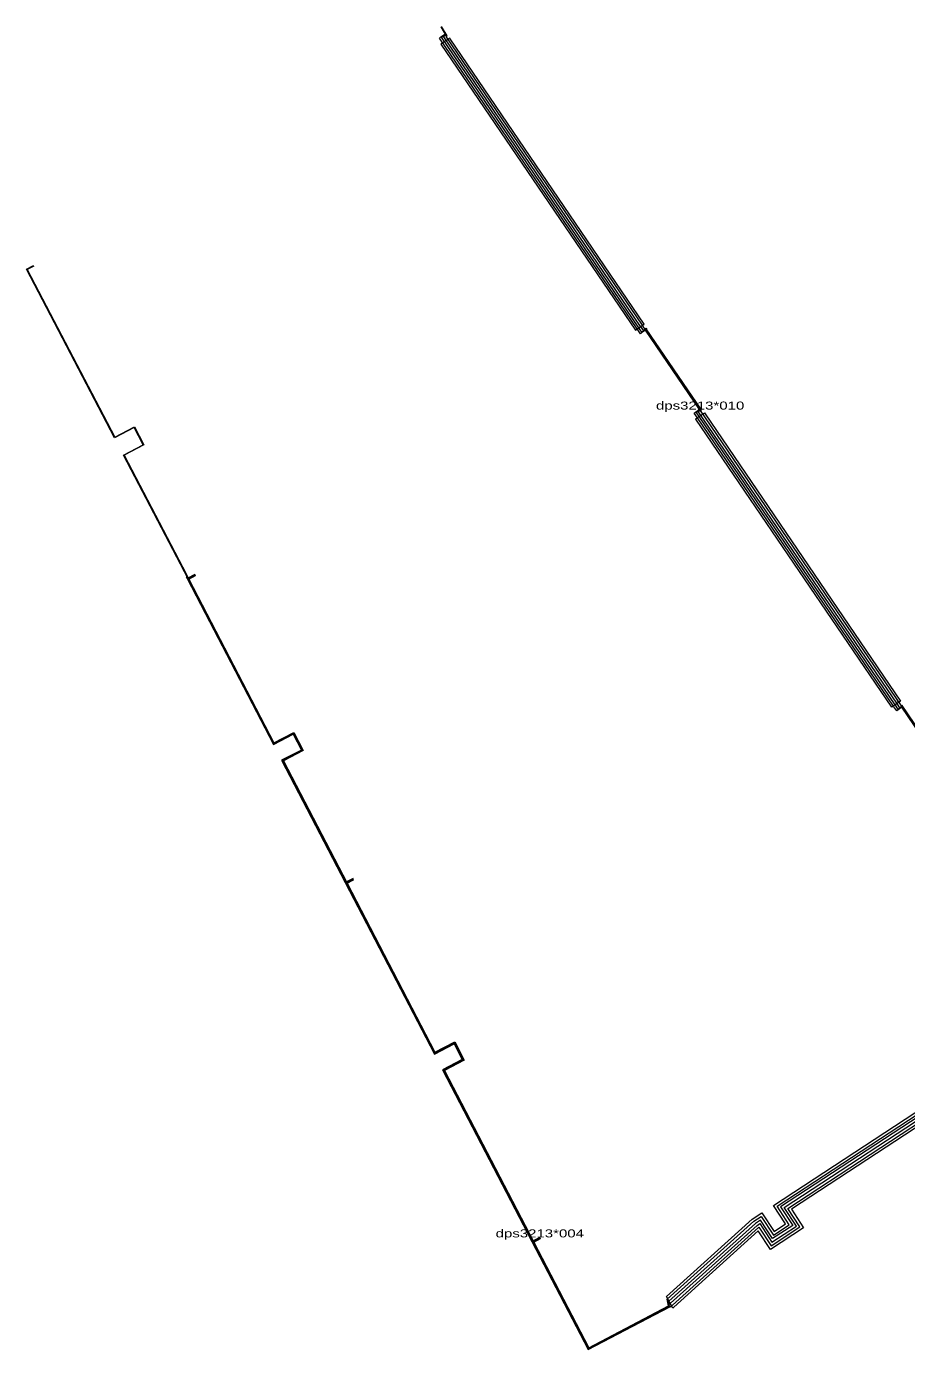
# Model space of a CAD drawing. Extents: x -473467 to -473049, y -1106745 to -1106181.
# Drawn here: x -473467 to -473368.1, y -1106572 to -1106423.3 of the extents above; entities that cross this region are included whole.
import ezdxf
from ezdxf.enums import TextEntityAlignment as Align

# ---------------------------------------------------------------- set-up
doc = ezdxf.new("R2010")
doc.units = 0
doc.header["$LTSCALE"] = 0.36
doc.header["$PDMODE"] = 32
doc.header["$PDSIZE"] = 0.18
doc.layers.add('11', color=7, linetype='Continuous', lineweight=13)
doc.layers.add('17', color=7, linetype='Continuous', lineweight=13)
doc.layers.add('19', color=7, linetype='Continuous')

msp = doc.modelspace()

# ---------------------------------------------------------------- linework, layer by layer
at = {"layer": '11'}
for points in [[(-473362.859, -1106508.966), (-473362.452, -1106508.691), (-473368.583, -1106499.672), (-473368.855, -1106499.858), (-473369.127, -1106499.459), (-473391.519, -1106466.551), (-473391.231, -1106466.356), (-473397.396, -1106457.287), (-473397.406, -1106457.272), (-473397.679, -1106457.458), (-473397.908, -1106457.12), (-473397.988, -1106457.003), (-473420.06, -1106424.535), (-473420.167, -1106424.378), (-473419.892, -1106424.19), (-473420.43, -1106423.291)], [(-473359.708, -1106529.352), (-473359.708, -1106529.352), (-473364.632, -1106521.935), (-473357.166, -1106516.999), (-473362.207, -1106509.406), (-473362.511, -1106508.948), (-473362.584, -1106508.841), (-473362.382, -1106508.704), (-473368.57, -1106499.603), (-473368.652, -1106499.659), (-473391.278, -1106466.448), (-473391.162, -1106466.369), (-473397.365, -1106457.244), (-473397.393, -1106457.203), (-473397.434, -1106457.231), (-473397.509, -1106457.281), (-473397.615, -1106457.124), (-473397.71, -1106456.985), (-473397.79, -1106456.868), (-473419.862, -1106424.4), (-473419.754, -1106424.327), (-473420.387, -1106423.265)], [(-473398.317, -1106457.373), (-473398.385, -1106457.273), (-473420.62, -1106424.565), (-473420.446, -1106424.447), (-473420.061, -1106424.184)], [(-473398.107, -1106457.255), (-473398.187, -1106457.138), (-473420.393, -1106424.471), (-473420.377, -1106424.46), (-473420.009, -1106424.21)], [(-473362.763, -1106543.227), (-473382.253, -1106555.985), (-473380.883, -1106558.077), (-473383.15, -1106559.56), (-473384.519, -1106557.469), (-473385.082, -1106557.837), (-473394.829, -1106566.605), (-473394.883, -1106566.653), (-473394.796, -1106567.142), (-473403.833, -1106571.891), (-473410.077, -1106559.922), (-473409.288, -1106559.51), (-473410.077, -1106559.922), (-473420.123, -1106540.615), (-473417.905, -1106539.463), (-473418.919, -1106537.512), (-473421.138, -1106538.666), (-473431.069, -1106519.572), (-473430.298, -1106519.17), (-473431.069, -1106519.572), (-473438.225, -1106505.815), (-473436.006, -1106504.662), (-473437.02, -1106502.711), (-473439.239, -1106503.866), (-473448.859, -1106485.374), (-473448.07, -1106484.962), (-473448.859, -1106485.374), (-473456.126, -1106471.452), (-473453.909, -1106470.295), (-473454.927, -1106468.344), (-473457.144, -1106469.501), (-473467.049, -1106450.567), (-473466.249, -1106450.156)], [(-473466.225, -1106450.205), (-473466.981, -1106450.588), (-473457.123, -1106469.434), (-473454.906, -1106468.277), (-473453.842, -1106470.316), (-473456.058, -1106471.473), (-473449.065, -1106484.872), (-473448.792, -1106485.395), (-473448.043, -1106485.006), (-473448.792, -1106485.395), (-473439.218, -1106503.798), (-473436.999, -1106502.644), (-473435.939, -1106504.684), (-473438.158, -1106505.836), (-473431.001, -1106519.593), (-473430.258, -1106519.212), (-473431.001, -1106519.593), (-473421.116, -1106538.599), (-473418.898, -1106537.445), (-473417.837, -1106539.484), (-473420.056, -1106540.637), (-473410.009, -1106559.943), (-473409.252, -1106559.553), (-473410.009, -1106559.943), (-473403.812, -1106571.823), (-473394.854, -1106567.116), (-473394.997, -1106566.365), (-473385.26, -1106557.606), (-473384.435, -1106557.066), (-473383.066, -1106559.158), (-473381.286, -1106557.993), (-473382.655, -1106555.901), (-473362.678, -1106542.825)], [(-473391.395, -1106466.346), (-473391.37, -1106466.329), (-473397.433, -1106457.411), (-473397.846, -1106457.692), (-473398.02, -1106457.81), (-473398.317, -1106457.373)], [(-473391.327, -1106466.36), (-473391.301, -1106466.342), (-473397.419, -1106457.342), (-473397.833, -1106457.623), (-473397.849, -1106457.634), (-473398.107, -1106457.255)], [(-473369.51, -1106499.749), (-473369.562, -1106499.673), (-473391.592, -1106467.266), (-473391.957, -1106466.728), (-473391.395, -1106466.346)], [(-473369.325, -1106499.594), (-473369.363, -1106499.538), (-473391.393, -1106467.131), (-473391.731, -1106466.635), (-473391.714, -1106466.623), (-473391.327, -1106466.36)], [(-473449.092, -1106485.144), (-473448.994, -1106485.331), (-473448.108, -1106484.869), (-473448.994, -1106485.331), (-473446.482, -1106490.16), (-473439.282, -1106504), (-473437.063, -1106502.846), (-473436.141, -1106504.62), (-473438.36, -1106505.772), (-473431.204, -1106519.53), (-473430.321, -1106519.069), (-473431.204, -1106519.53), (-473421.18, -1106538.801), (-473418.961, -1106537.647), (-473418.04, -1106539.42), (-473420.258, -1106540.573), (-473410.211, -1106559.879), (-473409.329, -1106559.418), (-473410.211, -1106559.879), (-473403.875, -1106572.026), (-473394.719, -1106567.214), (-473394.522, -1106567.111)], [(-473449.045, -1106485.127), (-473448.927, -1106485.353), (-473448.084, -1106484.912), (-473448.927, -1106485.353), (-473439.26, -1106503.933), (-473437.042, -1106502.779), (-473436.074, -1106504.641), (-473438.292, -1106505.793), (-473431.136, -1106519.551), (-473430.302, -1106519.119), (-473431.136, -1106519.551), (-473421.159, -1106538.734), (-473418.94, -1106537.58), (-473417.972, -1106539.442), (-473420.191, -1106540.594), (-473410.144, -1106559.901), (-473409.309, -1106559.468), (-473410.144, -1106559.901), (-473403.854, -1106571.958), (-473394.742, -1106567.17), (-473394.742, -1106567.17), (-473394.778, -1106566.95)], [(-473368.768, -1106499.133), (-473368.966, -1106499.268), (-473369.101, -1106499.069)], [(-473363.509, -1106509.289), (-473362.591, -1106508.665), (-473368.609, -1106499.811), (-473369.023, -1106500.092), (-473369.196, -1106500.21), (-473369.51, -1106499.749)], [(-473363.175, -1106509.122), (-473362.521, -1106508.678), (-473368.596, -1106499.742), (-473369.009, -1106500.023), (-473369.026, -1106500.034), (-473369.054, -1106499.993), (-473369.325, -1106499.594)], [(-473394.778, -1106566.95), (-473394.634, -1106566.821), (-473384.904, -1106558.068), (-473384.603, -1106557.871), (-473383.234, -1106559.963), (-473380.481, -1106558.161), (-473381.85, -1106556.069), (-473362.847, -1106543.63), (-473359.424, -1106548.861), (-473352.834, -1106544.573), (-473352.573, -1106544.403)], [(-473394.522, -1106567.111), (-473394.456, -1106567.052), (-473394.422, -1106567.021), (-473384.726, -1106558.299), (-473384.687, -1106558.274), (-473383.318, -1106560.365), (-473380.078, -1106558.245), (-473381.447, -1106556.153), (-473362.931, -1106544.032), (-473359.509, -1106549.263), (-473352.549, -1106544.734), (-473352.225, -1106544.524)]]:
    msp.add_lwpolyline(points, dxfattribs=at)
msp.add_point((-473397.406, -1106457.272), dxfattribs=at)
at = {"layer": '17'}
msp.add_line((-473394.382, -1106567.377), (-473394.522, -1106567.111), dxfattribs=at)
for points in [[(-473420.441, -1106425.255), (-473398.584, -1106457.408), (-473397.591, -1106456.733), (-473419.405, -1106424.645), (-473419.438, -1106424.596), (-473419.438, -1106424.596)], [(-473390.821, -1106466.692), (-473390.742, -1106466.809), (-473368.768, -1106499.133), (-473368.768, -1106499.133), (-473369.76, -1106499.808), (-473391.79, -1106467.401), (-473391.813, -1106467.367)]]:
    msp.add_lwpolyline(points, close=True, dxfattribs=at)
msp.add_lwpolyline([(-473394.522, -1106567.111), (-473395.081, -1106566.049), (-473385.437, -1106557.375), (-473384.351, -1106556.664), (-473382.982, -1106558.755), (-473381.688, -1106557.909), (-473383.058, -1106555.817), (-473362.594, -1106542.422), (-473359.171, -1106547.655), (-473353.689, -1106544.088), (-473353.049, -1106543.672), (-473352.256, -1106544.891), (-473359.593, -1106549.665), (-473363.015, -1106544.435), (-473381.045, -1106556.237), (-473379.676, -1106558.329), (-473383.402, -1106560.768), (-473384.771, -1106558.676), (-473394.246, -1106567.253), (-473394.382, -1106567.377)], dxfattribs=at)

# ---------------------------------------------------------------- texts
at = {"layer": '19', "width": 1.4}
for s, p in [('dps3213*010', (-473391.301, -1106466.342)), ('dps3213*004', (-473409.329, -1106559.418))]:
    msp.add_text(s, height=0.9, dxfattribs=at).set_placement(p, align=Align.CENTER)

doc.saveas('drawing.dxf')
